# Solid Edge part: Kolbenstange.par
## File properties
Sűrűség: 0,000 kg/m^3
Pontosság: 0,990
Author: bmolnar
Last saved by: bmolnar
Revision: 79
Username: bmolnar
Dokumentum tartalom típus: 0
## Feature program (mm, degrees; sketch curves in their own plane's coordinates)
base feature "unnamed BaseFeature 1"
thread "unnamed Thread 1"
sketch for "unnamed Protrusion 1" plane through (0, 0, -18.3) normal (0, 0, -1) x-axis (0, -1, 0)
  circle centre (0, 0) radius 10
extrude "unnamed Protrusion 1" add finite 13.4 along +normal
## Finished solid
Body 1: solid body, 17 faces, 23 edges, 8 vertices.
  Faces by surface: plane 8, cylinder 4, torus 3, cone 2
  Edges by curve: circle 13, line 6, ellipse 2, intersection 2
Bounding box of the edges (mm; curved faces can reach further): 20.000 x 20.000 x 52.700, from (-10, -10, -31.7) to (10, 10, 21).
Cylindrical faces by radius (mm): R2.9 x1, R4 x1, R5 x1, R10 x1
Conical faces (half-angle, radius in mm at the cone's reference point): 20 deg R3.5 x1, 60 deg R3.55 x1
Toroidal faces (ring radius, tube radius in mm): R3.3 r0.4 x2, R3.8 r1.2 x1
Planar faces by outward normal: +x 1, +z 3, -x 1, -z 1, oblique 2
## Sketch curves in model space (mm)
circle centre (0, 0, -18.3) radius 10
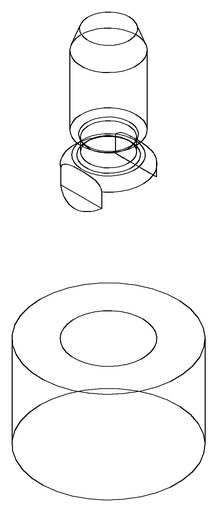
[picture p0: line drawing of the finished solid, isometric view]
